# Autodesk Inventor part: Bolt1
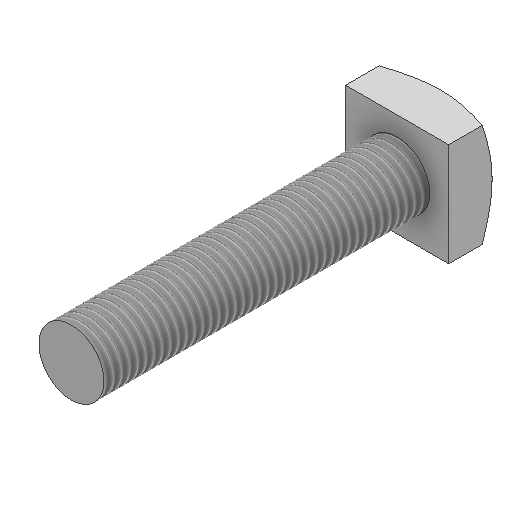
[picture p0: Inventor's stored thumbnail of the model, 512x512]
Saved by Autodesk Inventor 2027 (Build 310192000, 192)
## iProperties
Created: 2016-05
Part Number: Bolt1
Material: Generic
Document SubType Name: Modeling
Designer: CADCIM
Density: 1 g/cm^3
Appearance: Default
Author: CADCIM
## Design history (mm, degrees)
sketch "Sketch1"
  geometry: L1 (9.5, 9.5)-(-9.5, 9.5); L2 (-9.5, 9.5)-(-9.5, -9.5); L3 (-9.5, -9.5)-(9.5, -9.5); L4 (9.5, -9.5)-(9.5, 9.5); L5 (0, 0)-(0, 14.108); L6 (0, 0)-(-17.802, 0)
  constraints: 12 end point, 2 horizontal, 2 parallel, 2 perpendicular, 1 vertical, 2 other
  dimensions: "d0" = 19 distance of L3.end L1.start
extrude "Extrusion1" new body sketch "Sketch1" distance "d1" = 8; taper "d2" = 0 deg
sketch "Sketch3"
  geometry: L1 (9.5, 9.5)-(-9.5, 9.5) reference; C1 r 9.5 at (0, 0); 1 further point
  constraints: 1 centre point, 1 coincident, 1 tangent
extrude "Extrusion3" sketch "Sketch3" distance "d6" = 96; taper "d7" = 65 deg
sketch "Sketch4"
  geometry: C1 r 6 at (0, 0); 1 further point
  constraints: 1 centre point, 1 coincident
  dimensions: "d10" = 12 diameter of C1
extrude "Extrusion4" join sketch "Sketch4" distance "d11" = 60; taper "d12" = 0 deg
thread "Thread2" dims "d13" = 96, "d14" = 0
body "Solid1"
